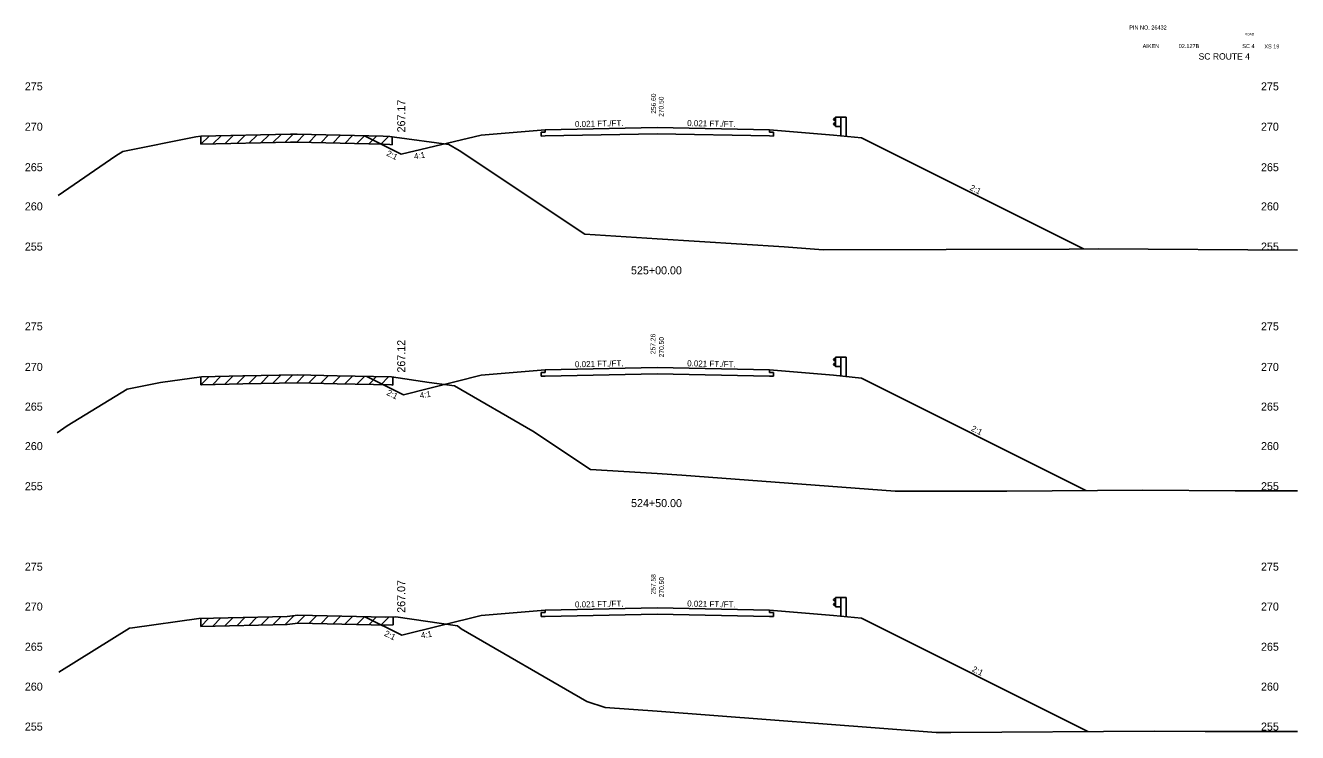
# Model space of a CAD drawing. Extents: x 883 to 1160, y 1002 to 4323.
# Drawn here: x 1001 to 1160, y 3084.9 to 3173.2 of the extents above; entities that cross this region are included whole.
import ezdxf

# ---------------------------------------------------------------- set-up
doc = ezdxf.new("R2010")
doc.units = 0
for name, color, linetype in [('Level 1', 7, 'Continuous'), ('Level 10', 7, 'Continuous'), ('Level 11', 7, 'Continuous'), ('Level 12', 7, 'Continuous'), ('Level 24', 7, 'Continuous'), ('Level 3', 7, 'Continuous'), ('Level 32', 7, 'Continuous'), ('Level 33', 7, 'Continuous'), ('Level 59', 7, 'Continuous'), ('Level 6', 7, 'Continuous'), ('Level 60', 7, 'Continuous'), ('Level 61', 7, 'Continuous'), ('Level 7', 7, 'Continuous')]:
    doc.layers.add(name, color=color, linetype=linetype)

msp = doc.modelspace()

# ---------------------------------------------------------------- linework, layer by layer
at = {"layer": 'Level 11'}
for p, q in [((1066, 3160.21), (1066, 3159.91)), ((1094, 3159.91), (1094, 3160.21)), ((1066, 3159.91), (1065.5, 3159.9)), ((1065.5, 3159.9), (1065.5, 3159.42)), ((1065.5, 3159.42), (1066, 3159.43)), ((1094.5, 3159.9), (1094, 3159.91)), ((1094, 3159.43), (1094.5, 3159.42)), ((1094.5, 3159.42), (1094.5, 3159.9)), ((1066, 3129.91), (1065.5, 3129.9)), ((1065.5, 3129.9), (1065.5, 3129.42)), ((1066, 3130.21), (1066, 3129.91)), ((1094, 3129.91), (1094, 3130.21)), ((1094.5, 3129.9), (1094, 3129.91)), ((1094.5, 3129.42), (1094.5, 3129.9)), ((1065.5, 3129.42), (1066, 3129.43)), ((1094, 3129.43), (1094.5, 3129.42)), ((1066, 3099.91), (1065.5, 3099.9)), ((1065.5, 3099.9), (1065.5, 3099.42)), ((1066, 3100.21), (1066, 3099.91)), ((1094, 3099.91), (1094, 3100.21)), ((1094.5, 3099.9), (1094, 3099.91)), ((1094.5, 3099.42), (1094.5, 3099.9)), ((1065.5, 3099.42), (1066, 3099.43)), ((1094, 3099.43), (1094.5, 3099.42))]:
    msp.add_line(p, q, dxfattribs=at)
at = {"layer": 'Level 12'}
for p, q in [((1080, 3159.72), (1066, 3159.43)), ((1094, 3159.43), (1080, 3159.72)), ((1080, 3129.72), (1066, 3129.43)), ((1094, 3129.43), (1080, 3129.72)), ((1080, 3099.72), (1066, 3099.43)), ((1094, 3099.43), (1080, 3099.72))]:
    msp.add_line(p, q, dxfattribs=at)
at = {"layer": 'Level 24'}
for p, q in [((1102.27, 3161.72), (1102, 3161.52)), ((1102.27, 3160.63), (1102.27, 3161.79)), ((1102.27, 3161.79), (1102.94, 3161.79)), ((1102.94, 3161.79), (1102.94, 3159.45)), ((1102.94, 3161.79), (1103.6, 3161.79)), ((1103.6, 3161.79), (1103.6, 3159.38)), ((1102, 3161.52), (1102, 3161.47)), ((1102, 3161.47), (1102.27, 3161.27)), ((1102, 3160.95), (1102.27, 3161.15)), ((1102, 3160.9), (1102, 3160.95)), ((1102.27, 3160.7), (1102, 3160.9)), ((1102.27, 3160.63), (1102.94, 3160.63)), ((1102.27, 3131.72), (1102, 3131.52)), ((1102, 3131.52), (1102, 3131.47)), ((1102, 3131.47), (1102.27, 3131.27)), ((1102.27, 3130.63), (1102.27, 3131.79)), ((1102.27, 3131.79), (1102.94, 3131.79)), ((1102.94, 3131.79), (1102.94, 3129.45)), ((1102.94, 3131.79), (1103.6, 3131.79)), ((1103.6, 3131.79), (1103.6, 3129.38)), ((1102, 3130.95), (1102.27, 3131.15)), ((1102, 3130.9), (1102, 3130.95)), ((1102.27, 3130.7), (1102, 3130.9)), ((1102.27, 3130.63), (1102.94, 3130.63)), ((1102.27, 3101.72), (1102, 3101.52)), ((1102, 3101.52), (1102, 3101.47)), ((1102, 3101.47), (1102.27, 3101.27)), ((1102.27, 3100.63), (1102.27, 3101.79)), ((1102.27, 3101.79), (1102.94, 3101.79)), ((1102.94, 3101.79), (1102.94, 3099.45)), ((1102.94, 3101.79), (1103.6, 3101.79)), ((1103.6, 3101.79), (1103.6, 3099.38)), ((1102, 3100.95), (1102.27, 3101.15)), ((1102, 3100.9), (1102, 3100.95)), ((1102.27, 3100.7), (1102, 3100.9)), ((1102.27, 3100.63), (1102.94, 3100.63))]:
    msp.add_line(p, q, dxfattribs=at)
at = {"layer": 'Level 59'}
for p, q in [((1066, 3160.21), (1080, 3160.5)), ((1080, 3160.5), (1094, 3160.21)), ((1066, 3130.21), (1080, 3130.5)), ((1080, 3130.5), (1094, 3130.21)), ((1066, 3100.21), (1080, 3100.5)), ((1080, 3100.5), (1094, 3100.21))]:
    msp.add_line(p, q, dxfattribs=at)
at = {"layer": 'Level 6'}
for p, q in [((1058, 3159.54), (1066, 3160.21)), ((1094, 3160.21), (1102, 3159.54)), ((1102, 3159.54), (1105.5, 3159.19)), ((1058, 3129.54), (1066, 3130.21)), ((1094, 3130.21), (1102, 3129.54)), ((1102, 3129.54), (1105.5, 3129.19)), ((1058, 3099.54), (1066, 3100.21)), ((1094, 3100.21), (1102, 3099.54)), ((1102, 3099.54), (1105.5, 3099.19))]:
    msp.add_line(p, q, dxfattribs=at)
at = {"layer": 'Level 60'}
for p, q in [((1013.22, 3157.51), (1022.33, 3159.31)), ((1022.33, 3159.31), (1022.95, 3159.4)), ((1022.95, 3159.4), (1034.16, 3159.65)), ((1034.16, 3159.65), (1035, 3159.66)), ((1035, 3159.66), (1045.74, 3159.39)), ((1045.74, 3159.39), (1046.58, 3159.38)), ((1046.58, 3159.38), (1047.17, 3159.29)), ((1047.17, 3159.29), (1053.96, 3158.35)), ((1005.12, 3151.98), (1012.32, 3156.96)), ((1012.32, 3156.96), (1013.22, 3157.51)), ((1053.96, 3158.35), (1055.26, 3157.6)), ((1055.26, 3157.6), (1070.93, 3147.18)), ((1070.93, 3147.18), (1080, 3146.6)), ((1080, 3146.6), (1095.87, 3145.6)), ((1095.87, 3145.6), (1100.72, 3145.23)), ((1100.72, 3145.23), (1131.45, 3145.31)), ((1131.45, 3145.31), (1135.14, 3145.34)), ((1135.14, 3145.34), (1160, 3145.17)), ((1013.75, 3127.83), (1017.92, 3128.65)), ((1017.92, 3128.65), (1023.06, 3129.37)), ((1023.06, 3129.37), (1028.21, 3129.48)), ((1028.21, 3129.48), (1035.03, 3129.61)), ((1035.03, 3129.61), (1039.99, 3129.49)), ((1039.99, 3129.49), (1046.77, 3129.34)), ((1046.77, 3129.34), (1051.51, 3128.65)), ((1051.51, 3128.65), (1054.64, 3128.22)), ((1006.27, 3123.22), (1013.75, 3127.83)), ((1054.64, 3128.22), (1064.43, 3122.58)), ((1005.02, 3122.36), (1006.27, 3123.22)), ((1064.43, 3122.58), (1071.63, 3117.79)), ((1071.63, 3117.79), (1080, 3117.26)), ((1080, 3117.26), (1083.08, 3117.06)), ((1083.08, 3117.06), (1109.72, 3115.06)), ((1109.72, 3115.06), (1123.68, 3115.09)), ((1123.68, 3115.09), (1140.67, 3115.21)), ((1140.67, 3115.21), (1152.22, 3115.13)), ((1152.22, 3115.13), (1160, 3115.13)), ((1014.41, 3098.02), (1022.7, 3099.18)), ((1022.7, 3099.18), (1033.76, 3099.4)), ((1033.76, 3099.4), (1035.06, 3099.57)), ((1035.06, 3099.57), (1046.08, 3099.33)), ((1046.08, 3099.33), (1047.32, 3099.37)), ((1047.32, 3099.37), (1055.03, 3098.26)), ((1055.03, 3098.26), (1055.48, 3097.89)), ((1005.2, 3092.48), (1014.06, 3097.94)), ((1014.06, 3097.94), (1014.41, 3098.02)), ((1055.48, 3097.89), (1071.2, 3088.82)), ((1071.2, 3088.82), (1073.47, 3088.07)), ((1073.47, 3088.07), (1080, 3087.58)), ((1080, 3087.58), (1114.84, 3084.93)), ((1114.84, 3084.93), (1116.66, 3084.92)), ((1116.66, 3084.92), (1142.13, 3085.11)), ((1142.13, 3085.11), (1148.47, 3085.06)), ((1148.47, 3085.06), (1160, 3085.06))]:
    msp.add_line(p, q, dxfattribs=at)
at = {"layer": 'Level 61'}
for p, q in [((1023.98, 3159.42), (1022.95, 3158.4)), ((1022.95, 3159.4), (1022.95, 3158.4)), ((1022.95, 3158.4), (1034.16, 3158.65)), ((1025.48, 3159.45), (1024.45, 3158.43)), ((1026.98, 3159.49), (1025.95, 3158.46)), ((1028.48, 3159.52), (1027.45, 3158.5)), ((1029.98, 3159.55), (1028.95, 3158.53)), ((1031.48, 3159.59), (1030.45, 3158.56)), ((1032.98, 3159.62), (1031.95, 3158.6)), ((1034.48, 3159.65), (1033.45, 3158.63)), ((1034.16, 3158.65), (1035, 3158.66)), ((1035.93, 3159.64), (1034.95, 3158.66)), ((1035, 3158.66), (1045.74, 3158.39)), ((1037.43, 3159.6), (1036.45, 3158.63)), ((1038.93, 3159.56), (1037.95, 3158.59)), ((1040.43, 3159.53), (1039.45, 3158.55)), ((1041.93, 3159.49), (1040.95, 3158.51)), ((1043.43, 3159.45), (1042.45, 3158.48)), ((1044.93, 3159.41), (1043.95, 3158.44)), ((1046.43, 3159.38), (1045.45, 3158.4)), ((1046.88, 3158.33), (1046.88, 3159.33)), ((1045.74, 3158.39), (1046.58, 3158.38)), ((1046.58, 3158.38), (1046.88, 3158.33)), ((1023.99, 3129.39), (1022.95, 3128.35)), ((1022.95, 3129.35), (1022.95, 3128.35)), ((1022.95, 3128.35), (1023.06, 3128.37)), ((1023.06, 3128.37), (1028.21, 3128.48)), ((1025.47, 3129.42), (1024.45, 3128.4)), ((1026.97, 3129.45), (1025.95, 3128.43)), ((1028.47, 3129.49), (1027.45, 3128.46)), ((1028.21, 3128.48), (1035.03, 3128.61)), ((1029.97, 3129.52), (1028.95, 3128.5)), ((1031.47, 3129.54), (1030.45, 3128.52)), ((1032.97, 3129.57), (1031.95, 3128.55)), ((1034.47, 3129.6), (1033.45, 3128.58)), ((1035.93, 3129.59), (1034.95, 3128.61)), ((1035.03, 3128.61), (1039.99, 3128.49)), ((1037.43, 3129.55), (1036.45, 3128.58)), ((1038.93, 3129.52), (1037.95, 3128.54)), ((1040.43, 3129.48), (1039.45, 3128.5)), ((1039.99, 3128.49), (1046.77, 3128.34)), ((1041.93, 3129.45), (1040.95, 3128.47)), ((1043.43, 3129.41), (1042.45, 3128.43)), ((1044.93, 3129.38), (1043.95, 3128.4)), ((1046.43, 3129.35), (1045.45, 3128.37)), ((1046.77, 3128.34), (1046.94, 3128.31)), ((1046.94, 3128.31), (1046.94, 3129.31)), ((1023.97, 3099.2), (1022.95, 3098.18)), ((1022.95, 3099.18), (1022.95, 3098.18)), ((1022.95, 3098.18), (1033.76, 3098.4)), ((1025.47, 3099.23), (1024.45, 3098.21)), ((1026.97, 3099.26), (1025.95, 3098.24)), ((1028.47, 3099.29), (1027.45, 3098.27)), ((1029.97, 3099.32), (1028.95, 3098.3)), ((1031.47, 3099.35), (1030.45, 3098.33)), ((1032.97, 3099.38), (1031.95, 3098.36)), ((1034.56, 3099.51), (1033.45, 3098.39)), ((1033.76, 3098.4), (1035.06, 3098.57)), ((1035.94, 3099.56), (1034.95, 3098.56)), ((1035.06, 3098.57), (1046.08, 3098.33)), ((1037.42, 3099.52), (1036.45, 3098.54)), ((1038.92, 3099.49), (1037.95, 3098.51)), ((1040.42, 3099.46), (1039.45, 3098.48)), ((1041.92, 3099.42), (1040.95, 3098.45)), ((1043.42, 3099.39), (1042.45, 3098.41)), ((1044.92, 3099.36), (1043.95, 3098.38)), ((1046.44, 3099.34), (1045.45, 3098.35)), ((1046.08, 3098.33), (1047.01, 3098.36)), ((1047.01, 3098.36), (1047.01, 3099.36))]:
    msp.add_line(p, q, dxfattribs=at)
at = {"layer": 'Level 7'}
for p, q in [((1043.43, 3159.45), (1048, 3157.17)), ((1048, 3157.17), (1058, 3159.54)), ((1105.5, 3159.19), (1133.24, 3145.32)), ((1043.71, 3129.41), (1048.29, 3127.12)), ((1058, 3129.54), (1048.29, 3127.12)), ((1105.5, 3129.19), (1133.56, 3115.16)), ((1043.44, 3099.39), (1048.09, 3097.07)), ((1058, 3099.54), (1048.09, 3097.07)), ((1105.5, 3099.19), (1133.79, 3085.05))]:
    msp.add_line(p, q, dxfattribs=at)

# ---------------------------------------------------------------- texts
at = {"layer": 'Level 1'}
for s, height, p in [('PIN NO. 26432', 0.5, (1138.97, 3172.73)), ('AIKEN', 0.5, (1140.64, 3170.41)), ('02.127B', 0.5, (1145.15, 3170.41)), ('SC ROUTE 4', 0.8, (1147.63, 3168.97)), ('SC 4', 0.5, (1153.09, 3170.41)), ('XS 19', 0.5, (1155.85, 3170.37)), ('525+00.00', 1, (1076.71, 3142.15)), ('524+50.00', 1, (1076.72, 3113.08))]:
    msp.add_text(s, height=height, dxfattribs=at).set_placement(p)
at = {"layer": 'Level 10'}
for s, p in [('256.60', (1079.83, 3162.2)), ('257.26', (1079.76, 3132.19)), ('257.58', (1079.8, 3102.17))]:
    msp.add_text(s, height=0.6, rotation=90, dxfattribs=at).set_placement(p)
at = {"layer": 'Level 3'}
for s, height, p in [('ROAD', 0.3, (1153.38, 3172)), (' 275', 1, (1000.6, 3165.13)), (' 275', 1, (1155.06, 3165.13)), (' 270', 1, (1000.6, 3160.09)), (' 270', 1, (1155.06, 3160.09)), (' 265', 1, (1000.6, 3155.03)), (' 265', 1, (1155.06, 3155.03)), (' 260', 1, (1000.6, 3150.14)), (' 260', 1, (1155.06, 3150.14)), (' 255', 1, (1000.6, 3145.12)), (' 255', 1, (1155.06, 3145.12)), (' 275', 1, (1000.6, 3135.16)), (' 275', 1, (1155.06, 3135.16)), (' 270', 1, (1000.6, 3130.09)), (' 270', 1, (1155.06, 3130.09)), (' 265', 1, (1000.6, 3125.13)), (' 265', 1, (1155.06, 3125.13)), (' 260', 1, (1000.6, 3120.2)), (' 260', 1, (1155.06, 3120.2)), (' 255', 1, (1000.6, 3115.19)), (' 255', 1, (1155.06, 3115.19)), (' 275', 1, (1000.6, 3105.14)), (' 275', 1, (1155.06, 3105.14)), (' 270', 1, (1000.6, 3100.16)), (' 270', 1, (1155.06, 3100.16)), (' 265', 1, (1000.6, 3095.14)), (' 265', 1, (1155.06, 3095.14)), (' 260', 1, (1000.6, 3090.16)), (' 260', 1, (1155.06, 3090.16)), (' 255', 1, (1000.6, 3085.17)), (' 255', 1, (1155.06, 3085.17))]:
    msp.add_text(s, height=height, dxfattribs=at).set_placement(p)
at = {"layer": 'Level 32'}
for s, rotation, p in [('0.021 FT./FT.', 1.1916, (1069.71, 3160.54)), ('0.021 FT./FT.', 358.8084, (1083.72, 3160.67)), ('2:1', 333.435, (1046.07, 3157.02)), ('4:1', 9.4623, (1049.66, 3156.51)), ('2:1', 333.435, (1118.97, 3152.73)), ('0.021 FT./FT.', 1.1916, (1069.71, 3130.54)), ('0.021 FT./FT.', 358.8084, (1083.72, 3130.67)), ('2:1', 333.435, (1046.1, 3127.13)), ('4:1', 9.4623, (1050.37, 3126.64)), ('2:1', 333.435, (1119.14, 3122.65)), ('0.021 FT./FT.', 1.1916, (1069.71, 3100.54)), ('0.021 FT./FT.', 358.8084, (1083.72, 3100.67)), ('2:1', 333.435, (1045.81, 3097.05)), ('4:1', 9.4623, (1050.52, 3096.67)), ('2:1', 333.435, (1119.25, 3092.6))]:
    msp.add_text(s, height=0.75, rotation=rotation, dxfattribs=at).set_placement(p)
at = {"layer": 'Level 33'}
for s, p in [('267.17', (1048.5, 3159.88)), ('267.12', (1048.5, 3129.88)), ('267.07', (1048.5, 3099.88))]:
    msp.add_text(s, height=1, rotation=90, dxfattribs=at).set_placement(p)
at = {"layer": 'Level 59'}
for p in [(1080.79, 3161.59), (1080.82, 3131.56), (1080.82, 3101.59)]:
    msp.add_text(' 270.50', height=0.6, rotation=90, dxfattribs=at).set_placement(p)

doc.saveas('drawing.dxf')
